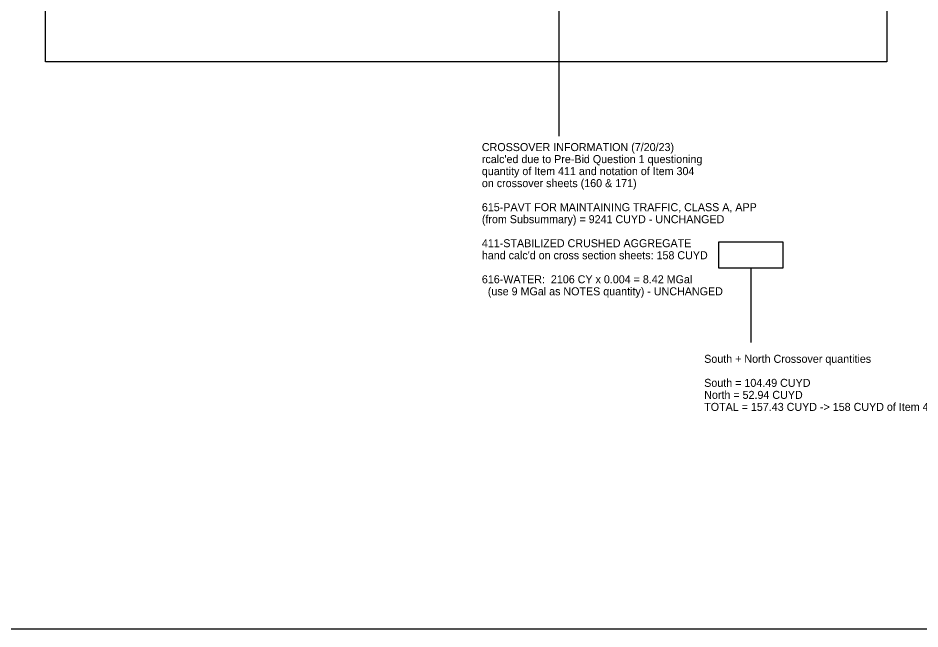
# Model space of a CAD drawing. Extents: x 1820207 to 1820557, y 740216 to 740315.
# Drawn here: x 1820368.89 to 1820384.66, y 740244.01 to 740254.68 of the extents above; entities that cross this region are included whole.
import ezdxf

# ---------------------------------------------------------------- set-up
doc = ezdxf.new("R2010")
doc.units = 0
for name, color, linetype in [('SC_Scratch4', 7, 'Continuous'), ('SC_Shading1', 7, 'Continuous'), ('SH_Text', 7, 'Continuous')]:
    doc.layers.add(name, color=color, linetype=linetype)

msp = doc.modelspace()

# ---------------------------------------------------------------- linework, layer by layer
at = {"layer": 'SC_Scratch4'}
msp.add_lwpolyline([(1820369.372, 740275.98), (1820384.08, 740275.98), (1820384.08, 740253.918), (1820369.372, 740253.918)], close=True, dxfattribs=at)
at = {"layer": 'SC_Shading1'}
for p, q in [((1820378.349, 740265.302), (1820378.349, 740252.621)), ((1820381.705, 740250.314), (1820381.705, 740249.013))]:
    msp.add_line(p, q, dxfattribs=at)
msp.add_lwpolyline([(1820381.146, 740250.776), (1820382.265, 740250.776), (1820382.265, 740250.314), (1820381.146, 740250.314)], close=True, dxfattribs=at)
at = {"layer": 'SH_Text'}
msp.add_lwpolyline([(1820217.201, 740244.009), (1820515.724, 740244.009), (1820515.724, 740286.62), (1820217.201, 740286.62)], close=True, dxfattribs=at)

# ---------------------------------------------------------------- texts
at = {"layer": 'SC_Shading1'}
for s, p in [('CROSSOVER INFORMATION (7/20/23)', (1820377.002, 740252.359)), ("rcalc'ed due to Pre-Bid Question 1 questioning ", (1820377.002, 740252.149)), ('quantity of Item 411 and notation of Item 304 ', (1820377.002, 740251.939)), ('on crossover sheets (160 & 171)', (1820377.002, 740251.729)), ('615-PAVT FOR MAINTAINING TRAFFIC, CLASS A, APP', (1820377.002, 740251.309)), ('(from Subsummary) = 9241 CUYD - UNCHANGED', (1820377.002, 740251.099)), ('411-STABILIZED CRUSHED AGGREGATE', (1820377.002, 740250.679)), ("hand calc'd on cross section sheets: 158 CUYD", (1820377.002, 740250.469)), ('616-WATER:  2106 CY x 0.004 = 8.42 MGal', (1820377.002, 740250.049)), ('  (use 9 MGal as NOTES quantity) - UNCHANGED', (1820377.002, 740249.839)), ('South + North Crossover quantities', (1820380.889, 740248.659)), ('South = 104.49 CUYD', (1820380.889, 740248.239)), ('North = 52.94 CUYD', (1820380.889, 740248.029)), ('TOTAL = 157.43 CUYD -> 158 CUYD of Item 411', (1820380.889, 740247.819))]:
    msp.add_text(s, height=0.14, dxfattribs=at).set_placement(p)

doc.saveas('drawing.dxf')
